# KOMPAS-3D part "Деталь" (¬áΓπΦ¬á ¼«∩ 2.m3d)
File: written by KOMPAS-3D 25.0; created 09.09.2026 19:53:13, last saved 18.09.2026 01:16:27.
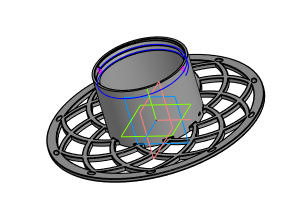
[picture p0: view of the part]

Document properties: Автор: PC; Полное имя файла: C:\Users\PC\Documents\катушка моя 2.m3d

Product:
- Part/product: Деталь

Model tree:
1. Эскиз:1
2. Элемент выдавливания:1
     Расстояние 1 = 4
3. Эскиз:2
4. Элемент выдавливания:2
     Расстояние 2 = 10
5. Эскиз:3
6. Элемент выдавливания:3
     Расстояние 2 = 10
7. Эскиз:4
8. Элемент выдавливания:4
     Расстояние 1 = 60
9. Эскиз:5
10. Элемент выдавливания:5
     Расстояние 2 = 10
11. Эскиз:9
12. Спираль:1
     Число витков = 1.5; Шаг = 5.33333; Высота = 8; Диаметр 1 = 83; Диаметр 2 = 10; Координата Y = 47; Нутация = -90
13. Элемент по траектории:1
     Длина траектории = 391.21
14. Скругление:1
     Радиус = 1
15. Скругление:2
     Радиус = 0.5
16. Скругление:3
     Радиус = 0.5
17. Скругление:4
     Радиус = 0.5
18. Скругление:5
     Радиус = 1
19. Скругление:6
     Радиус = 1
20. Скругление:7
     Радиус = 1
21. Скругление:8
     Радиус = 1
22. Скругление:9
     Радиус = 1
23. Скругление:10
     Радиус = 1
24. Эскиз:10
25. Элемент выдавливания:6
     Расстояние 1 = 1000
